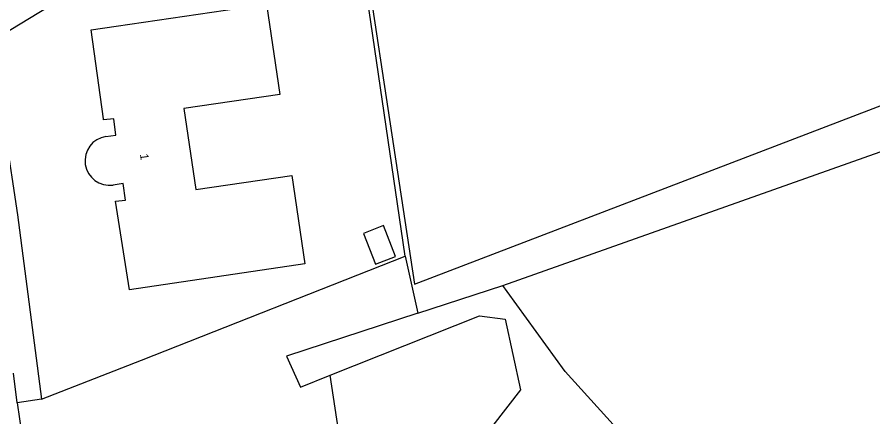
# Model space of a CAD drawing. Extents: x 162722 to 165099, y 384721 to 386283.
# Drawn here: x 164182.3 to 164285.4, y 385036.1 to 385084.3 of the extents above; entities that cross this region are included whole.
import ezdxf

# ---------------------------------------------------------------- set-up
doc = ezdxf.new("R2010")
doc.units = 0
for name, color, linetype in [('IMGEO_Grasland_overig', 7, 'Continuous'), ('IMGEO_Groenvoorziening', 7, 'Continuous'), ('IMGEO_Loofbos', 7, 'Continuous'), ('IMGEO_Pand', 7, 'Continuous'), ('IMGEO_Pand_nummerreeks', 7, 'Continuous'), ('IMGEO_Rijbaan_lokaal_open', 7, 'Continuous'), ('IMGEO_Voetpad_open', 7, 'Continuous')]:
    doc.layers.add(name, color=color, linetype=linetype)

msp = doc.modelspace()

# ---------------------------------------------------------------- linework, layer by layer
at = {"layer": 'IMGEO_Grasland_overig'}
for points in [[(164244.01, 385128.16), (164244.69, 385122.21), (164221.69, 385107.99), (164230.18, 385052.07), (164300.52, 385079.04), (164292.21, 385149.4), (164255.66, 385126.31), (164253.22, 385131.71)], [(164229.04, 385055.46), (164221.49, 385107.05), (164179.29, 385081.39)], [(164229.04, 385055.46), (164230.58, 385048.58)]]:
    msp.add_lwpolyline(points, dxfattribs=at)
at = {"layer": 'IMGEO_Groenvoorziening'}
for points in [[(164185.26, 385038.21), (164197.28, 385042.9), (164229.04, 385055.46)], [(164221.84, 385029.17), (164220.03, 385041.08)]]:
    msp.add_lwpolyline(points, dxfattribs=at)
msp.add_arc((164226.03, 385118.69), 106.8, 303.5929, 311.1685, dxfattribs=at)
at = {"layer": 'IMGEO_Loofbos'}
for points in [[(164240.8, 385051.93), (164304.18, 385074.38), (164304.04, 385077.11), (164303.96, 385078.11), (164305.34, 385078.79)], [(164230.58, 385048.58), (164240.8, 385051.93)], [(164265.34, 385027.02), (164255.25, 385033.87), (164248.33, 385041.53), (164241.35, 385051.17), (164240.8, 385051.93)], [(164230.58, 385048.58), (164214.76, 385043.38), (164216.45, 385039.65), (164220.03, 385041.08)], [(164220.03, 385041.08), (164237.99, 385048.25), (164241.08, 385047.87), (164242.95, 385039.35), (164236.28, 385030.72), (164232.48, 385024.48), (164234.3, 385020.15)]]:
    msp.add_lwpolyline(points, dxfattribs=at)
at = {"layer": 'IMGEO_Pand'}
for points in [[(164193.02, 385069.87), (164194.22, 385070.04), (164193.96, 385072.01), (164192.73, 385071.88), (164192.71, 385072), (164191.23, 385082.74), (164194.26, 385083.18), (164212.34, 385085.85)], [(164212.34, 385085.85), (164213.95, 385074.96), (164202.38, 385073.26), (164203.83, 385063.48), (164215.39, 385065.18), (164216.96, 385054.52), (164195.84, 385051.4), (164194.17, 385062.08), (164195.37, 385062.2), (164195.08, 385064.19), (164193.89, 385064.02)], [(164225.49, 385054.48), (164227.9, 385055.42), (164226.44, 385059.14), (164224.03, 385058.2), (164225.49, 385054.48)]]:
    msp.add_lwpolyline(points, dxfattribs=at)
msp.add_arc((164193.45, 385066.95), 2.96, 98.4167, 278.3947, dxfattribs=at)
at = {"layer": 'IMGEO_Rijbaan_lokaal_open'}
for points in [[(164182.34, 385037.75), (164181.88, 385041.34)], [(164182.34, 385037.75), (164182.89, 385033.92)]]:
    msp.add_lwpolyline(points, dxfattribs=at)
at = {"layer": 'IMGEO_Voetpad_open'}
for points in [[(164180.89, 385070.32), (164182.36, 385060.42), (164185.26, 385038.21)], [(164185.26, 385038.21), (164182.34, 385037.75)]]:
    msp.add_lwpolyline(points, dxfattribs=at)

# ---------------------------------------------------------------- texts
at = {"layer": 'IMGEO_Pand_nummerreeks'}
msp.add_text('1', height=1, rotation=278.1721, dxfattribs=at).set_placement((164197.11, 385067.73))

doc.saveas('drawing.dxf')
